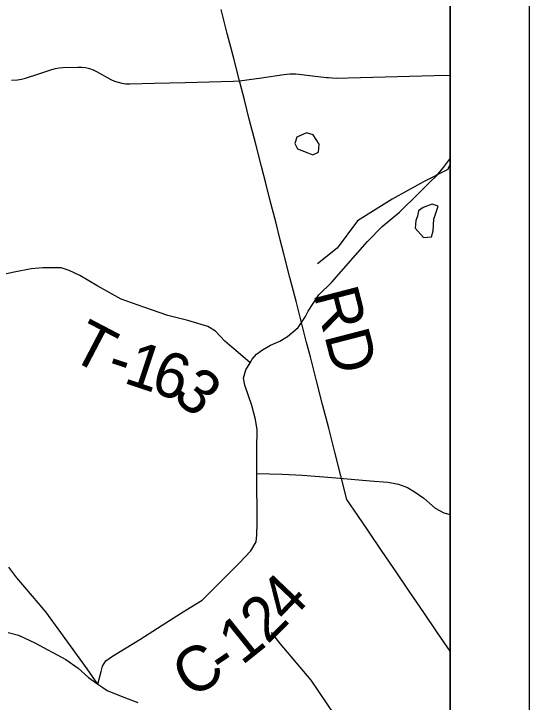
# Model space of a CAD drawing. Extents: x -6.1 to 38, y -7.7 to 22.
# Drawn here: x 8.347 to 9, y 15.345 to 16.217 of the extents above; entities that cross this region are included whole.
import ezdxf

# ---------------------------------------------------------------- set-up
doc = ezdxf.new("R2010")
doc.units = 0
for name, color, linetype in [('GM_X_Corporation', 7, 'Continuous'), ('GM_X_County_Road', 7, 'Continuous'), ('GM_X_County_Road_Text', 7, 'Continuous'), ('GM_X_Minor_Lake', 7, 'Continuous'), ('GM_X_Minor_River', 7, 'Continuous'), ('GM_X_State_Route', 7, 'Continuous'), ('GM_X_Township_Road', 7, 'Continuous'), ('GM_X_Township_Road_Text', 7, 'Continuous'), ('SH_Data', 7, 'Continuous')]:
    doc.layers.add(name, color=color, linetype=linetype)

msp = doc.modelspace()

# ---------------------------------------------------------------- linework, layer by layer
at = {"layer": 'GM_X_Corporation'}
for points in [[(8.9, 14.85918), (8.9, 19.87135), (8.53815, 19.88018), (8.02661, 19.88922), (8.02125, 19.70471), (8.02079, 19.68982), (8.0189, 19.62846), (7.99279, 18.77986), (7.97287, 17.92154), (7.97183, 17.87641), (7.95308, 17.06692), (7.95307, 17.06643), (7.93594, 16.3267), (7.92512, 16.10977), (7.91657, 15.91251), (7.90988, 15.74002), (7.90533, 15.62285), (7.88899, 15.0865), (7.88923, 14.89059), (8.1023, 14.88375), (8.27757, 14.87811), (8.6137, 14.86789)], [(8.9, 14.68725), (8.9, 19.53649), (8.77571, 19.53237), (8.77312, 19.53228), (6.99327, 19.47331), (6.99349, 19.46054), (7.03821, 16.8882), (7.05054, 16.17866), (7.07262, 15.21743), (7.07601, 15.03919), (7.07603, 15.03845), (7.07902, 14.88093), (7.08348, 14.64684), (7.55487, 14.65733), (8.5875, 14.68029)]]:
    msp.add_lwpolyline(points, close=True, dxfattribs=at)
at = {"layer": 'GM_X_County_Road'}
for points in [[(8.9, 15.40977), (8.88396, 15.43331), (8.86647, 15.45898), (8.84897, 15.48466), (8.83148, 15.51033), (8.81399, 15.53601), (8.7965, 15.56169), (8.78287, 15.5817), (8.76925, 15.6017), (8.76152, 15.6318), (8.75379, 15.66189), (8.74606, 15.69198), (8.73833, 15.72208), (8.7306, 15.75217), (8.72287, 15.78226), (8.71814, 15.80067), (8.7134, 15.81908), (8.70907, 15.83592), (8.70475, 15.85276), (8.69702, 15.88285), (8.68929, 15.91294), (8.68435, 15.93217), (8.67941, 15.95139), (8.67168, 15.98148), (8.66632, 16.00235), (8.66097, 16.02322), (8.65322, 16.0533), (8.64549, 16.08339), (8.63931, 16.10744), (8.63312, 16.13148), (8.62538, 16.16158), (8.61764, 16.19167), (8.60991, 16.22176)], [(8.64665, 15.77502), (8.64934, 15.77956), (8.65473, 15.78559), (8.66206, 15.79119), (8.67219, 15.79702), (8.68404, 15.8024), (8.69395, 15.80801), (8.70732, 15.81943), (8.71659, 15.83366), (8.7202, 15.84037), (8.73362, 15.86081), (8.74978, 15.87633), (8.79505, 15.92849), (8.81379, 15.94746), (8.83578, 15.96556), (8.86013, 15.98949), (8.87436, 16.00393), (8.88276, 16.01147), (8.8916, 16.02182), (8.89914, 16.03216), (8.9, 16.03355)], [(8.4536, 15.36816), (8.45789, 15.38409), (8.45973, 15.39104), (8.46381, 15.39757), (8.47239, 15.4037), (8.50711, 15.42454), (8.5351, 15.44292), (8.55859, 15.45762), (8.57067, 15.46531), (8.58597, 15.47457), (8.59783, 15.48621), (8.63253, 15.52135), (8.6474, 15.53708), (8.6543, 15.54829), (8.65516, 15.55734), (8.65559, 15.57178), (8.65516, 15.63457), (8.65516, 15.66597), (8.65559, 15.68989), (8.65343, 15.70314), (8.64891, 15.72099), (8.63986, 15.74658), (8.63814, 15.75563), (8.64115, 15.76598), (8.64665, 15.77502)]]:
    msp.add_lwpolyline(points, dxfattribs=at)
at = {"layer": 'GM_X_Minor_Lake'}
for p, q in [((8.71216, 16.04363), (8.71972, 16.04061)), ((8.85997, 15.96699), (8.85847, 15.96054))]:
    msp.add_line(p, q, dxfattribs=at)
for points in [[(8.71972, 16.04061), (8.72615, 16.03797), (8.73331, 16.0414), (8.73404, 16.05164), (8.72646, 16.06337), (8.71777, 16.066), (8.7057, 16.0603), (8.70308, 16.05233), (8.7065, 16.04552), (8.71216, 16.04363)], [(8.85847, 15.96054), (8.85622, 15.95485), (8.85549, 15.94537), (8.86609, 15.93364), (8.87628, 15.93442), (8.87815, 15.94201), (8.87925, 15.95679), (8.88449, 15.9731), (8.87693, 15.97574), (8.86562, 15.97154), (8.85997, 15.96699)]]:
    msp.add_lwpolyline(points, dxfattribs=at)
at = {"layer": 'GM_X_Minor_River'}
for points in [[(8.9, 16.0262), (8.89758, 16.02202), (8.89683, 16.01936), (8.86591, 16.00376), (8.82633, 15.98208), (8.7826, 15.9547), (8.75664, 15.91978), (8.73178, 15.90003)], [(8.9, 15.21466), (8.87768, 15.22835), (8.83566, 15.27223), (8.80047, 15.30589), (8.75284, 15.33043), (8.72404, 15.3732), (8.68466, 15.41974), (8.67368, 15.43336)]]:
    msp.add_lwpolyline(points, dxfattribs=at)
at = {"layer": 'GM_X_State_Route'}
for points in [[(8.34003, 15.43373), (8.35311, 15.43025), (8.37394, 15.42045), (8.41316, 15.39921), (8.42888, 15.38838), (8.44196, 15.37653), (8.4536, 15.36816)], [(8.4536, 15.36816), (8.46005, 15.36376), (8.46576, 15.36001), (8.48342, 15.35305), (8.50446, 15.34508)]]:
    msp.add_lwpolyline(points, dxfattribs=at)
at = {"layer": 'GM_X_Township_Road'}
for points in [[(8.34443, 16.1326), (8.35211, 16.13279), (8.35713, 16.13361), (8.36206, 16.13496), (8.37885, 16.14059), (8.39565, 16.14621), (8.40016, 16.14748), (8.4048, 16.14829), (8.40944, 16.14865), (8.42839, 16.14913), (8.43337, 16.149), (8.43825, 16.14836), (8.44308, 16.14719), (8.44777, 16.14555), (8.45222, 16.14341), (8.47032, 16.13358), (8.47482, 16.13145), (8.47946, 16.1298), (8.48429, 16.12864), (8.48922, 16.12799), (8.4942, 16.12786), (8.52525, 16.12867), (8.54488, 16.12918), (8.56451, 16.12969), (8.59488, 16.13048), (8.62525, 16.13127), (8.63312, 16.13148), (8.66119, 16.13564), (8.68926, 16.1398), (8.69301, 16.14025), (8.69675, 16.14051), (8.70054, 16.14058), (8.70429, 16.14044), (8.70808, 16.1401), (8.72578, 16.13806), (8.74347, 16.13602), (8.74603, 16.13575), (8.75067, 16.13539), (8.75536, 16.13519), (8.78641, 16.13599), (8.81747, 16.13678), (8.84853, 16.13759), (8.87958, 16.13838), (8.9, 16.13891)], [(8.64665, 15.77502), (8.62854, 15.7904), (8.62348, 15.79464), (8.61464, 15.8024), (8.6029, 15.81479), (8.59309, 15.82072), (8.56765, 15.82826), (8.54257, 15.83453), (8.5119, 15.84509), (8.48338, 15.85521), (8.45387, 15.8719), (8.43093, 15.88524), (8.41743, 15.89185), (8.4073, 15.89508), (8.38423, 15.89508), (8.36936, 15.89357), (8.34803, 15.88969), (8.32238, 15.88388), (8.306, 15.88172), (8.28272, 15.88193), (8.2644, 15.88193), (8.24974, 15.88086), (8.23767, 15.88258), (8.22603, 15.88624)], [(8.65516, 15.63457), (8.68706, 15.63407), (8.71292, 15.63256), (8.75064, 15.62954), (8.79849, 15.62567), (8.82112, 15.62372), (8.83448, 15.62114), (8.84569, 15.61704), (8.85561, 15.61101), (8.86638, 15.60347), (8.88104, 15.59096), (8.892, 15.58482), (8.9, 15.58286)], [(8.4536, 15.36816), (8.44012, 15.38777), (8.40683, 15.43373), (8.38804, 15.45967), (8.36148, 15.49092), (8.35136, 15.50265), (8.34113, 15.51639)]]:
    msp.add_lwpolyline(points, dxfattribs=at)
at = {"layer": 'SH_Data'}
for p, q in [((9, 21), (9, 14)), ((8.9, 20.9), (8.9, 14.1))]:
    msp.add_line(p, q, dxfattribs=at)

# ---------------------------------------------------------------- texts
at = {"layer": 'GM_X_County_Road_Text'}
for s, height, rotation, p in [('RD', 0.056818, 284.51645, (8.72647, 15.8629)), ('4', 0.05682, 46.31379, (8.69409, 15.44337)), ('2', 0.05682, 45.1854, (8.66857, 15.41767)), ('1', 0.05682, 38.79724, (8.63616, 15.39111)), ('C', 0.05682, 32.24368, (8.57164, 15.34894)), ('-', 0.05682, 34.30196, (8.61297, 15.37506))]:
    msp.add_text(s, height=height, rotation=rotation, dxfattribs=at).set_placement(p)
at = {"layer": 'GM_X_Township_Road_Text'}
for s, rotation, p in [('T', 332.38078, (8.41599, 15.78114)), ('1', 341.53319, (8.48485, 15.75008)), ('6', 341.98575, (8.51851, 15.73884)), ('-', 341.2982, (8.4625, 15.75765)), ('3', 319.73003, (8.54673, 15.73084))]:
    msp.add_text(s, height=0.05682, rotation=rotation, dxfattribs=at).set_placement(p)

doc.saveas('drawing.dxf')
